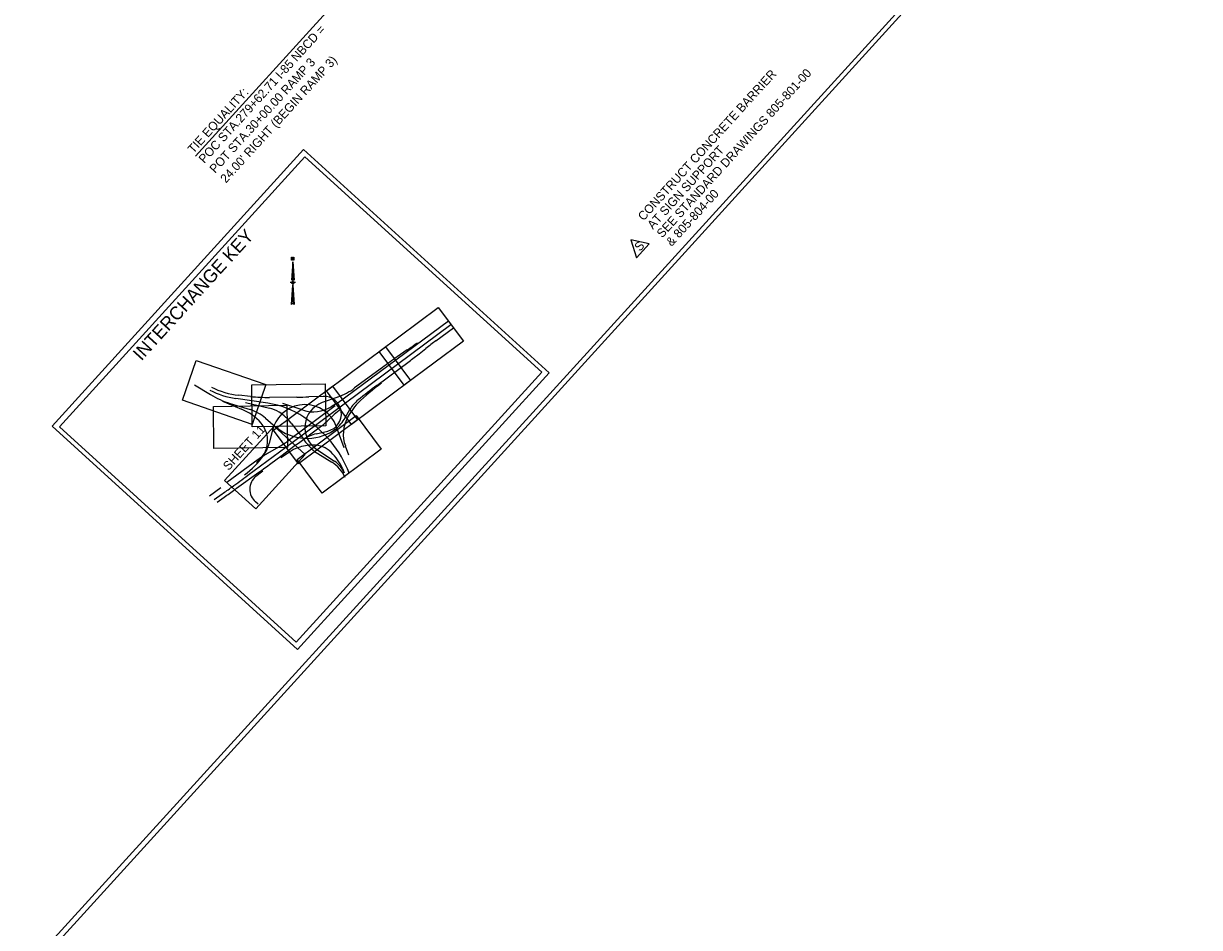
# Model space of a CAD drawing. Extents: x 1608705 to 1610581, y 1091647 to 1093887.
# Drawn here: x 1609761 to 1610564, y 1092394 to 1093011 of the extents above; entities that cross this region are included whole.
import ezdxf

# ---------------------------------------------------------------- set-up
doc = ezdxf.new("R2010")
doc.units = 0
for name, color, linetype in [('Level 2', 7, 'Continuous'), ('Level 3', 7, 'Continuous'), ('Plan_Clip', 7, 'Continuous'), ('RD_HC_CL', 7, 'Continuous'), ('RD_SHT_Misc1', 7, 'Continuous'), ('RD_SHT_TX', 7, 'Continuous'), ('RD_TX_Misc1', 7, 'Continuous')]:
    doc.layers.add(name, color=color, linetype=linetype)

msp = doc.modelspace()

# ---------------------------------------------------------------- linework, layer by layer
at = {"layer": 'Level 2'}
for p, q in [((1609944.64, 1092848.1), (1609943.7, 1092835.67)), ((1609946.43, 1092833.87), (1609942.87, 1092833.87)), ((1609944.64, 1092836.94), (1609943.7, 1092835.67)), ((1609944.64, 1092836.94), (1609944.64, 1092832.05)), ((1609944.64, 1092832.05), (1609945.58, 1092818.93)), ((1609945.58, 1092818.93), (1609944.64, 1092819.98))]:
    msp.add_line(p, q, dxfattribs=at)
for points in [[(1608729.11, 1092645.4), (1609856.11, 1093884.55), (1610563.72, 1093240.99), (1609436.73, 1092001.83)], [(1609944.64, 1092848.1), (1609945.58, 1092835.67), (1609944.64, 1092836.94)], [(1609944.64, 1092832.05), (1609944.64, 1092819.98), (1609943.7, 1092818.93)], [(1610003.72, 1092786.93), (1610044.05, 1092816.91), (1610061.17, 1092793.88), (1610020.84, 1092763.9)], [(1609967.61, 1092760.09), (1610007.93, 1092790.06), (1610025.05, 1092767.04), (1609984.73, 1092737.06)], [(1609916.92, 1092737.14), (1609869.43, 1092753.58), (1609878.82, 1092780.7), (1609926.31, 1092764.26)], [(1609967.3, 1092736.1), (1609917.06, 1092735.36), (1609916.63, 1092764.05), (1609966.88, 1092764.79)], [(1609931.49, 1092733.24), (1609971.82, 1092763.22), (1609988.94, 1092740.19), (1609948.61, 1092710.21)], [(1609941.13, 1092721.46), (1609890.89, 1092720.72), (1609890.46, 1092749.41), (1609940.71, 1092750.15)], [(1609947.65, 1092713.23), (1609987.98, 1092743.21), (1610005.1, 1092720.18), (1609964.77, 1092690.2)], [(1609898.14, 1092698.81), (1609931.95, 1092735.99), (1609953.18, 1092716.68), (1609919.37, 1092679.51)]]:
    msp.add_lwpolyline(points, close=True, dxfattribs=at)
msp.add_lwpolyline([(1609945.45, 1092849.15), (1609945.11, 1092849.15), (1609944.17, 1092850.65), (1609944.17, 1092850.43), (1609944.17, 1092849.15), (1609943.83, 1092849.15), (1609943.83, 1092851.23), (1609944.17, 1092851.23), (1609945.11, 1092849.84), (1609945.11, 1092849.96), (1609945.11, 1092851.23), (1609945.45, 1092851.23), (1609945.45, 1092849.15)], dxfattribs=at)
msp.add_circle((1609944.65, 1092833.87), 0.946, dxfattribs=at)
at = {"layer": 'Level 3'}
msp.add_lwpolyline([(1609898.14, 1092698.81), (1609931.95, 1092735.99), (1609953.18, 1092716.68), (1609919.37, 1092679.51)], close=True, dxfattribs=at)
at = {"layer": 'Plan_Clip'}
msp.add_lwpolyline([(1609149.57, 1092364.39), (1609089.98, 1092453.43), (1608942.04, 1092657.59), (1608947.36, 1092661.14), (1608865.54, 1092773.4), (1609629.05, 1093625.07), (1609624.58, 1093628.85), (1609641.66, 1093647.8), (1609756.72, 1093668.33), (1609768.78, 1093644.04), (1609859.36, 1093621.37), (1610115.12, 1093602.27), (1610196.6, 1093489.1), (1610193.26, 1093486.62), (1610273.82, 1093378.23), (1610243.45, 1093357.42), (1610329.63, 1093200.98), (1610402.66, 1093068.39), (1609510.9, 1092089.32)], dxfattribs=at)
msp.add_lwpolyline([(1609149.57, 1092364.39), (1609089.98, 1092453.43), (1608942.04, 1092657.59), (1608947.36, 1092661.14), (1608865.54, 1092773.4), (1609629.05, 1093625.07), (1609624.58, 1093628.85), (1609641.66, 1093647.8), (1609756.72, 1093668.33), (1609768.78, 1093644.04), (1609859.36, 1093621.37), (1610115.12, 1093602.27), (1610196.6, 1093489.1), (1610193.26, 1093486.62), (1610273.82, 1093378.23), (1610243.45, 1093357.42), (1610329.63, 1093200.98), (1610402.66, 1093068.39), (1609510.9, 1092089.32)], dxfattribs=at)
at = {"layer": 'RD_HC_CL'}
for p, q in [((1610050.91, 1092807.68), (1609974.76, 1092751.08)), ((1609944.24, 1092724.81), (1610052.62, 1092805.38)), ((1610042.39, 1092794.19), (1610054.34, 1092803.07)), ((1610022.82, 1092787.96), (1610015.88, 1092783.17)), ((1610030.89, 1092785.33), (1610035.62, 1092789.03)), ((1610005.91, 1092776.05), (1609986.93, 1092761.99)), ((1610001.97, 1092763.7), (1610024.12, 1092780.16)), ((1609877.53, 1092764.16), (1609888.43, 1092757.51)), ((1609896.62, 1092752.96), (1609909.66, 1092747.57)), ((1609901.96, 1092751.41), (1609915.5, 1092747.23)), ((1609927.65, 1092751.52), (1609905.9, 1092754.77)), ((1609915.89, 1092756.16), (1609907.85, 1092757.01)), ((1609912.48, 1092752.15), (1609928.74, 1092748.24)), ((1609947.41, 1092755.72), (1609928.88, 1092755.55)), ((1609951.88, 1092746.8), (1609937.85, 1092751.32)), ((1609973.6, 1092749.77), (1609942.34, 1092726.53)), ((1609965.42, 1092756.27), (1609955.56, 1092755.91)), ((1609975.43, 1092755.82), (1609964.82, 1092751.99)), ((1609974.55, 1092751.37), (1609970.83, 1092749.08)), ((1609968.06, 1092739.31), (1609973.05, 1092743.84)), ((1609979.79, 1092740.57), (1609983.65, 1092747.18)), ((1609982.28, 1092741.95), (1609984.91, 1092746.44)), ((1609926.16, 1092741.36), (1609932.99, 1092735.5)), ((1609943.57, 1092738.05), (1609952.16, 1092726.72)), ((1609948.52, 1092724.42), (1609963.48, 1092735.54)), ((1609979.88, 1092721.21), (1609974.34, 1092735.88)), ((1609930.89, 1092733.35), (1609928.58, 1092724.13)), ((1609942.34, 1092726.53), (1609942.01, 1092726.28)), ((1609960.71, 1092730.74), (1609968.6, 1092732.59)), ((1609914.09, 1092702.4), (1609944.24, 1092724.81)), ((1609934.99, 1092721.66), (1609927.51, 1092717.3)), ((1609936.42, 1092714.52), (1609942.34, 1092718.31)), ((1609936.45, 1092715.44), (1609946.4, 1092722.84)), ((1609946.4, 1092722.84), (1609948.52, 1092724.42)), ((1609961.05, 1092720.01), (1609973.11, 1092712.1)), ((1609983.02, 1092716.05), (1609980.63, 1092722.37)), ((1609921.06, 1092713.09), (1609899.76, 1092697.57)), ((1609929.69, 1092710.42), (1609936.45, 1092715.44)), ((1609961.81, 1092717.18), (1609971.28, 1092711.41)), ((1609906.33, 1092693.48), (1609921.6, 1092704.49)), ((1609919.53, 1092701.72), (1609924.21, 1092705.49)), ((1609978.53, 1092707.08), (1609979.8, 1092704.09)), ((1609895.52, 1092693.89), (1609887.9, 1092688.18)), ((1609899.62, 1092697.46), (1609899.47, 1092697.35)), ((1609890.96, 1092685.81), (1609896.4, 1092689.62)), ((1609893.12, 1092684.13), (1609897.9, 1092687.49)), ((1609921.06, 1092682.65), (1609919.26, 1092684.21))]:
    msp.add_line(p, q, dxfattribs=at)
for centre, radius, start, end in [((1609818.51, 1093084.36), 360, 304.57794, 305.93788), ((1610247.32, 1092518.52), 343.5, 126.62559, 128.04643), ((1610220.19, 1092486.76), 360, 124.57794, 126.5281), ((1609819.19, 1093055.84), 343.5, 306.62559, 308.04643), ((1609914.36, 1092811.43), 57.3, 242.62682, 261.50654), ((1609913.37, 1092809.52), 52.8, 242.62682, 263.9996), ((1609960.15, 1092798.15), 45, 289.8521, 306.5281), ((1610112.62, 1092620.77), 180, 126.62559, 133.35895), ((1610206.9, 1092488.02), 343.5, 126.62559, 129.29258), ((1609919.67, 1092808.74), 60, 238.62682, 252.83713), ((1609927.81, 1092869.54), 114, 263.9996, 270.53703), ((1609918.79, 1092692.18), 60, 56.13007, 81.50654), ((1609953.01, 1092727.82), 22.8, 20.71665, 160.12545), ((1609944.6, 1093055.71), 300, 270.53703, 272.09472), ((1609970.93, 1092735.06), 18, 109.8521, 236.724), ((1609965.86, 1092744.27), 12, 283.22578, 92.09472), ((1610005.11, 1092734.63), 24.86, 129.29258, 149.68185), ((1610005.11, 1092734.63), 23.4, 133.35895, 149.68185), ((1609895.91, 1092714.3), 36, 41.06232, 67.54601), ((1609906.64, 1092718.57), 30, 49.42945, 72.83713), ((1609923.42, 1092726.07), 22.8, 58.5149, 76.50654), ((1609919.66, 1092719.93), 30, 37.15085, 58.5149), ((1609958.88, 1092768.5), 22.8, 252.13194, 301.62559), ((1609903.59, 1092669.54), 87.26, 39.63338, 56.13007), ((1610013.43, 1092699.46), 60, 126.62559, 132.29445), ((1610001.96, 1092730.44), 22.8, 149.68185, 200.71665), ((1609909.48, 1092726.12), 18, 14.04535, 41.06232), ((1609953.01, 1092727.82), 22.8, 160.12545, 165.94914), ((1609954.46, 1092760.57), 33, 229.42945, 303.62785), ((1609927.69, 1092783.69), 60, 306.62559, 312.29445), ((1609960.1, 1092752.08), 22.8, 303.62785, 329.68185), ((1609909.48, 1092726.12), 18, 323.57458, 14.04535), ((1609897.27, 1092786.48), 75, 300.20081, 306.62559), ((1609965.93, 1092708.54), 22.8, 103.22578, 127.60447), ((1609999.98, 1092762.95), 60, 217.15085, 224.99109), ((1609905.3, 1092729.96), 24, 324.50243, 345.94914), ((1609958.51, 1092693.04), 30, 110.11938, 122.62559), ((1609958.51, 1092693.04), 30, 90.02488, 110.11938), ((1609973.67, 1092736.65), 22.8, 224.99109, 238.63503), ((1609958.51, 1092705.04), 18, 46.37367, 90.02488), ((1609913.04, 1092677.36), 75, 20.71665, 39.63338), ((1609948.16, 1092694.19), 33, 23.00726, 46.37367), ((1609875.99, 1092750.86), 60, 306.49468, 324.50243), ((1609876.16, 1092750.71), 59.42, 317.78867, 323.57458), ((1609965.24, 1092652.48), 75, 120.20081, 126.08721), ((1609518.05, 1093264.18), 690, 305.79282, 306.62559), ((1609959.41, 1092691.94), 22.8, 23.00726, 58.63503), ((1609963.24, 1092697.05), 18, 23.00726, 56.724), ((1609441.52, 1093338.13), 792.14, 305.63683, 306.62559), ((1609926.69, 1092692.85), 11.4, 128.8796, 229.29826), ((1609441.52, 1093338.13), 792.14, 305.04683, 305.63683), ((1609441.52, 1093338.13), 794.75, 305.67708, 305.79282), ((1609441.52, 1093338.13), 794.75, 305.04683, 305.67708)]:
    msp.add_arc(centre, radius, start, end, dxfattribs=at)
at = {"layer": 'RD_SHT_TX'}
msp.add_line((1609993.85, 1093047.3), (1609878.33, 1092920.29), dxfattribs=at)
msp.add_lwpolyline([(1610175.38, 1092863.14), (1610179.34, 1092850.74), (1610188.1, 1092860.38)], close=True, dxfattribs=at)
at = {"layer": 'RD_TX_Misc1'}
for points in [[(1609780.37, 1092735.99), (1609952.06, 1092924.76), (1610119.7, 1092772.29), (1609948.01, 1092583.52)], [(1609952.99, 1092919.85), (1610114.73, 1092772.76), (1609947.07, 1092588.43), (1609785.34, 1092735.52)]]:
    msp.add_lwpolyline(points, close=True, dxfattribs=at)

# ---------------------------------------------------------------- texts
at = {"layer": 'RD_SHT_Misc1'}
for s, height, p in [('INTERCHANGE KEY', 9, (1609841.31, 1092780.05)), ('SHEET 11', 6, (1609900.87, 1092705.26))]:
    msp.add_text(s, height=height, rotation=47.71377, dxfattribs=at).set_placement(p)
at = {"layer": 'RD_SHT_TX'}
for s, rotation, p in [('POC STA.279+62.71 I-85 NBCD =', 47.71215, (1609884.25, 1092914.91)), ('POT STA.30+00.00 RAMP 3', 47.71215, (1609891.65, 1092908.18)), ("24.00' RIGHT (BEGIN RAMP 3)", 47.71215, (1609899.05, 1092901.45)), ('CONSTRUCT CONCRETE BARRIER ', 47.71377, (1610184.17, 1092875.68)), ('SEE STANDARD DRAWINGS 805-801-00', 47.71377, (1610196.96, 1092864.05)), ('TIE EQUALITY:', 47.71215, (1609876.85, 1092921.64)), ('AT SIGN SUPPORT', 47.71377, (1610190.57, 1092869.87)), ('& 805-804-00', 47.71377, (1610203.36, 1092858.23)), ('S', 47.71377, (1610181.71, 1092854.83))]:
    msp.add_text(s, height=6, rotation=rotation, dxfattribs=at).set_placement(p)

doc.saveas('drawing.dxf')
